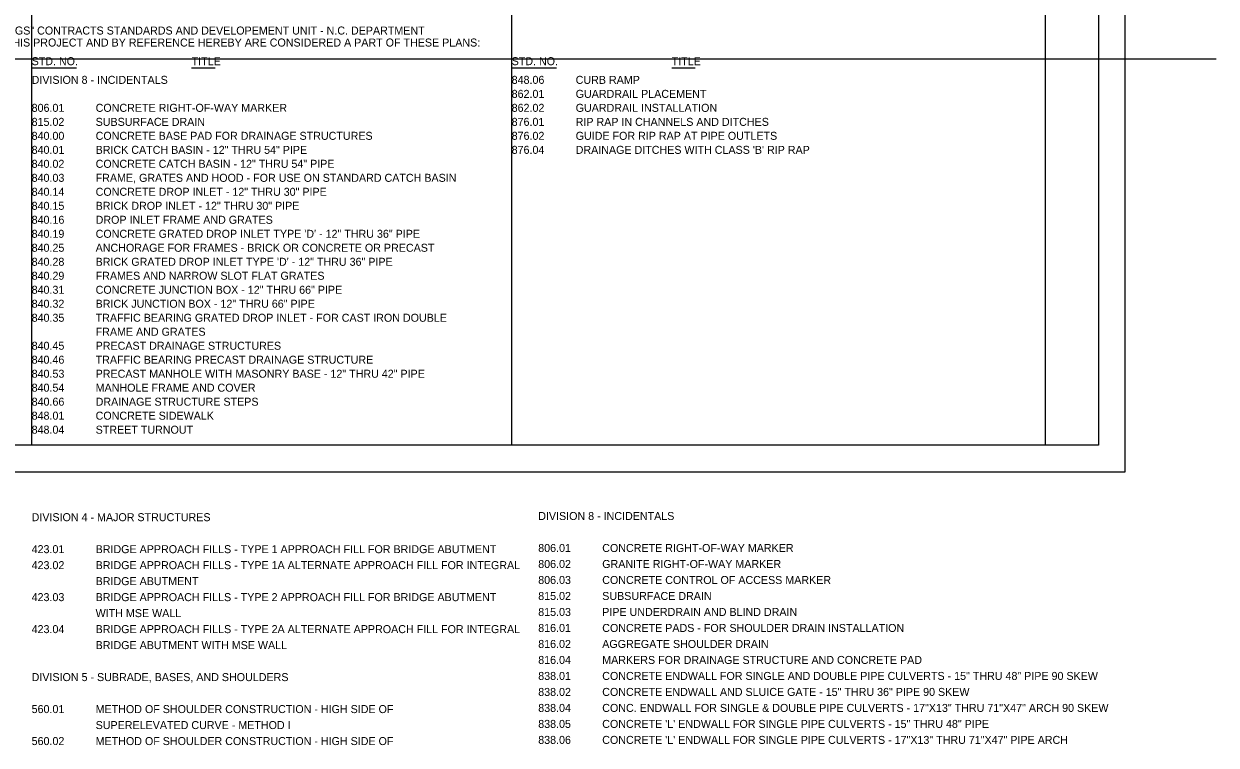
# Model space of a CAD drawing. Extents: x 573076.3 to 573113.7, y -55253.8 to -55199.3.
# Drawn here: x 573091.37 to 573113.72, y -55226.42 to -55212.89 of the extents above; entities that cross this region are included whole.
import ezdxf

# ---------------------------------------------------------------- set-up
doc = ezdxf.new("R2010")
doc.units = 0
for name, color, linetype in [('Prop DSN Text', 7, 'Continuous'), ('Scratch_Level_1', 7, 'Continuous'), ('Sheet Plan CELL', 7, 'Continuous'), ('Sheet Plot Border Inside CELL', 7, 'Continuous')]:
    doc.layers.add(name, color=color, linetype=linetype)

msp = doc.modelspace()

# ---------------------------------------------------------------- linework, layer by layer
at = {"layer": 'Prop DSN Text'}
for p, q in [((573091.514, -55213.717), (573092.356, -55213.717)), ((573094.514, -55213.717), (573094.957, -55213.717)), ((573100.514, -55213.717), (573101.356, -55213.717)), ((573103.514, -55213.717), (573103.957, -55213.717))]:
    msp.add_line(p, q, dxfattribs=at)
at = {"layer": 'Scratch_Level_1'}
for p, q in [((573091.514, -55202.55), (573091.514, -55220.798)), ((573100.514, -55202.55), (573100.514, -55220.798)), ((573110.514, -55202.55), (573110.514, -55220.798)), ((573082.514, -55213.549), (573113.722, -55213.549))]:
    msp.add_line(p, q, dxfattribs=at)
at = {"layer": 'Sheet Plan CELL'}
msp.add_lwpolyline([(573081.514, -55199.798), (573111.514, -55199.798), (573111.514, -55220.798), (573081.514, -55220.798)], close=True, dxfattribs=at)
at = {"layer": 'Sheet Plot Border Inside CELL'}
msp.add_lwpolyline([(573112.014, -55199.298), (573078.014, -55199.298), (573078.014, -55221.298), (573112.014, -55221.298)], close=True, dxfattribs=at)

# ---------------------------------------------------------------- texts
at = {"layer": 'Prop DSN Text'}
for s, p in [('THE FOLLOWING ROADWAY STANDARDS AS APPEAR IN "ROADWAY STANDARD DRAWINGS" CONTRACTS STANDARDS AND DEVELOPEMENT UNIT - N.C. DEPARTMENT', (573082.514, -55213.092)), ('OF TRANSPORTATION - RALEIGH, N.C., DATED JANUARY 16, 2024 ARE APPLICABLE TO THIS PROJECT AND BY REFERENCE HEREBY ARE CONSIDERED A PART OF THESE PLANS:', (573082.514, -55213.317)), ('STD. NO.', (573091.514, -55213.667)), ('TITLE', (573094.514, -55213.667)), ('STD. NO.', (573100.514, -55213.667)), ('TITLE', (573103.514, -55213.667)), ('DIVISION 8 - INCIDENTALS', (573091.514, -55214.017)), ('848.06', (573100.514, -55214.017)), ('CURB RAMP', (573101.714, -55214.017)), ('862.01', (573100.514, -55214.28)), ('GUARDRAIL PLACEMENT', (573101.714, -55214.28)), ('806.01', (573091.514, -55214.542)), ('CONCRETE RIGHT-OF-WAY MARKER', (573092.714, -55214.542)), ('862.02', (573100.514, -55214.542)), ('GUARDRAIL INSTALLATION', (573101.714, -55214.542)), ('815.02', (573091.514, -55214.805)), ('SUBSURFACE DRAIN', (573092.714, -55214.805)), ('876.01', (573100.514, -55214.805)), ('RIP RAP IN CHANNELS AND DITCHES', (573101.714, -55214.805)), ('840.00', (573091.514, -55215.067)), ('CONCRETE BASE PAD FOR DRAINAGE STRUCTURES', (573092.714, -55215.067)), ('876.02', (573100.514, -55215.067)), ('GUIDE FOR RIP RAP AT PIPE OUTLETS', (573101.714, -55215.067)), ('840.01', (573091.514, -55215.33)), ('BRICK CATCH BASIN - 12" THRU 54" PIPE', (573092.714, -55215.33)), ('876.04', (573100.514, -55215.33)), ("DRAINAGE DITCHES WITH CLASS 'B' RIP RAP", (573101.714, -55215.33)), ('840.02', (573091.514, -55215.592)), ('CONCRETE CATCH BASIN - 12" THRU 54" PIPE', (573092.714, -55215.592)), ('840.03', (573091.514, -55215.855)), ('FRAME, GRATES AND HOOD - FOR USE ON STANDARD CATCH BASIN', (573092.714, -55215.855)), ('840.14', (573091.514, -55216.117)), ('CONCRETE DROP INLET - 12" THRU 30" PIPE', (573092.714, -55216.117)), ('840.15', (573091.514, -55216.38)), ('BRICK DROP INLET - 12" THRU 30" PIPE', (573092.714, -55216.38)), ('840.16', (573091.514, -55216.642)), ('DROP INLET FRAME AND GRATES', (573092.714, -55216.642)), ('840.19', (573091.514, -55216.905)), ('CONCRETE GRATED DROP INLET TYPE \'D\' - 12" THRU 36" PIPE', (573092.714, -55216.905)), ('840.25', (573091.514, -55217.167)), ('ANCHORAGE FOR FRAMES - BRICK OR CONCRETE OR PRECAST', (573092.714, -55217.167)), ('840.28', (573091.514, -55217.43)), ('BRICK GRATED DROP INLET TYPE \'D\' - 12" THRU 36" PIPE', (573092.714, -55217.43)), ('840.29', (573091.514, -55217.692)), ('FRAMES AND NARROW SLOT FLAT GRATES', (573092.714, -55217.692)), ('840.31', (573091.514, -55217.955)), ('CONCRETE JUNCTION BOX - 12" THRU 66" PIPE', (573092.714, -55217.955)), ('840.32', (573091.514, -55218.217)), ('BRICK JUNCTION BOX - 12" THRU 66" PIPE', (573092.714, -55218.217)), ('840.35', (573091.514, -55218.48)), ('TRAFFIC BEARING GRATED DROP INLET - FOR CAST IRON DOUBLE ', (573092.714, -55218.48)), ('FRAME AND GRATES', (573092.714, -55218.742)), ('840.45', (573091.514, -55219.005)), ('PRECAST DRAINAGE STRUCTURES', (573092.714, -55219.005)), ('840.46', (573091.514, -55219.267)), ('TRAFFIC BEARING PRECAST DRAINAGE STRUCTURE', (573092.714, -55219.267)), ('840.53', (573091.514, -55219.53)), ('PRECAST MANHOLE WITH MASONRY BASE - 12" THRU 42" PIPE', (573092.714, -55219.53)), ('840.54', (573091.514, -55219.792)), ('MANHOLE FRAME AND COVER', (573092.714, -55219.792)), ('840.66', (573091.514, -55220.055)), ('DRAINAGE STRUCTURE STEPS', (573092.714, -55220.055)), ('848.01', (573091.514, -55220.317)), ('CONCRETE SIDEWALK', (573092.714, -55220.317)), ('848.04', (573091.514, -55220.58)), ('STREET TURNOUT', (573092.714, -55220.58)), ('DIVISION 4 - MAJOR STRUCTURES', (573091.514, -55222.221)), ('DIVISION 8 - INCIDENTALS', (573101.012, -55222.199)), ('423.01', (573091.514, -55222.821)), ('BRIDGE APPROACH FILLS - TYPE 1 APPROACH FILL FOR BRIDGE ABUTMENT', (573092.714, -55222.821)), ('806.01', (573101.012, -55222.799)), ('CONCRETE RIGHT-OF-WAY MARKER', (573102.212, -55222.799)), ('423.02', (573091.514, -55223.121)), ('BRIDGE APPROACH FILLS - TYPE 1A ALTERNATE APPROACH FILL FOR INTEGRAL', (573092.714, -55223.121)), ('806.02', (573101.012, -55223.099)), ('GRANITE RIGHT-OF-WAY MARKER', (573102.212, -55223.099)), ('806.03', (573101.012, -55223.399)), ('CONCRETE CONTROL OF ACCESS MARKER', (573102.212, -55223.399)), ('BRIDGE ABUTMENT', (573092.714, -55223.421)), ('423.03', (573091.514, -55223.721)), ('BRIDGE APPROACH FILLS - TYPE 2 APPROACH FILL FOR BRIDGE ABUTMENT', (573092.714, -55223.721)), ('815.02', (573101.012, -55223.699)), ('SUBSURFACE DRAIN', (573102.212, -55223.699)), ('WITH MSE WALL', (573092.714, -55224.021)), ('815.03', (573101.012, -55223.999)), ('PIPE UNDERDRAIN AND BLIND DRAIN', (573102.212, -55223.999)), ('816.01', (573101.012, -55224.299)), ('CONCRETE PADS - FOR SHOULDER DRAIN INSTALLATION', (573102.212, -55224.299)), ('423.04', (573091.514, -55224.321)), ('BRIDGE APPROACH FILLS - TYPE 2A ALTERNATE APPROACH FILL FOR INTEGRAL', (573092.714, -55224.321)), ('BRIDGE ABUTMENT WITH MSE WALL', (573092.714, -55224.621)), ('816.02', (573101.012, -55224.599)), ('AGGREGATE SHOULDER DRAIN', (573102.212, -55224.599)), ('816.04', (573101.012, -55224.899)), ('MARKERS FOR DRAINAGE STRUCTURE AND CONCRETE PAD', (573102.212, -55224.899)), ('838.01', (573101.012, -55225.199)), ('CONCRETE ENDWALL FOR SINGLE AND DOUBLE PIPE CULVERTS - 15" THRU 48" PIPE 90 SKEW', (573102.212, -55225.199)), ('DIVISION 5 - SUBRADE, BASES, AND SHOULDERS', (573091.514, -55225.221)), ('838.02', (573101.012, -55225.499)), ('CONCRETE ENDWALL AND SLUICE GATE - 15" THRU 36" PIPE 90 SKEW', (573102.212, -55225.499)), ('560.01', (573091.514, -55225.821)), ('METHOD OF SHOULDER CONSTRUCTION - HIGH SIDE OF', (573092.714, -55225.821)), ('838.04', (573101.012, -55225.799)), ('CONC. ENDWALL FOR SINGLE & DOUBLE PIPE CULVERTS - 17"X13" THRU 71"X47" ARCH 90 SKEW', (573102.212, -55225.799)), ('SUPERELEVATED CURVE - METHOD I', (573092.714, -55226.121)), ('838.05', (573101.012, -55226.099)), ('CONCRETE \'L\' ENDWALL FOR SINGLE PIPE CULVERTS - 15" THRU 48" PIPE', (573102.212, -55226.099)), ('560.02', (573091.514, -55226.421)), ('METHOD OF SHOULDER CONSTRUCTION - HIGH SIDE OF', (573092.714, -55226.421)), ('838.06', (573101.012, -55226.399)), ('CONCRETE \'L\' ENDWALL FOR SINGLE PIPE CULVERTS - 17"X13" THRU 71"X47" PIPE ARCH', (573102.212, -55226.399))]:
    msp.add_text(s, height=0.15, dxfattribs=at).set_placement(p)

doc.saveas('drawing.dxf')
